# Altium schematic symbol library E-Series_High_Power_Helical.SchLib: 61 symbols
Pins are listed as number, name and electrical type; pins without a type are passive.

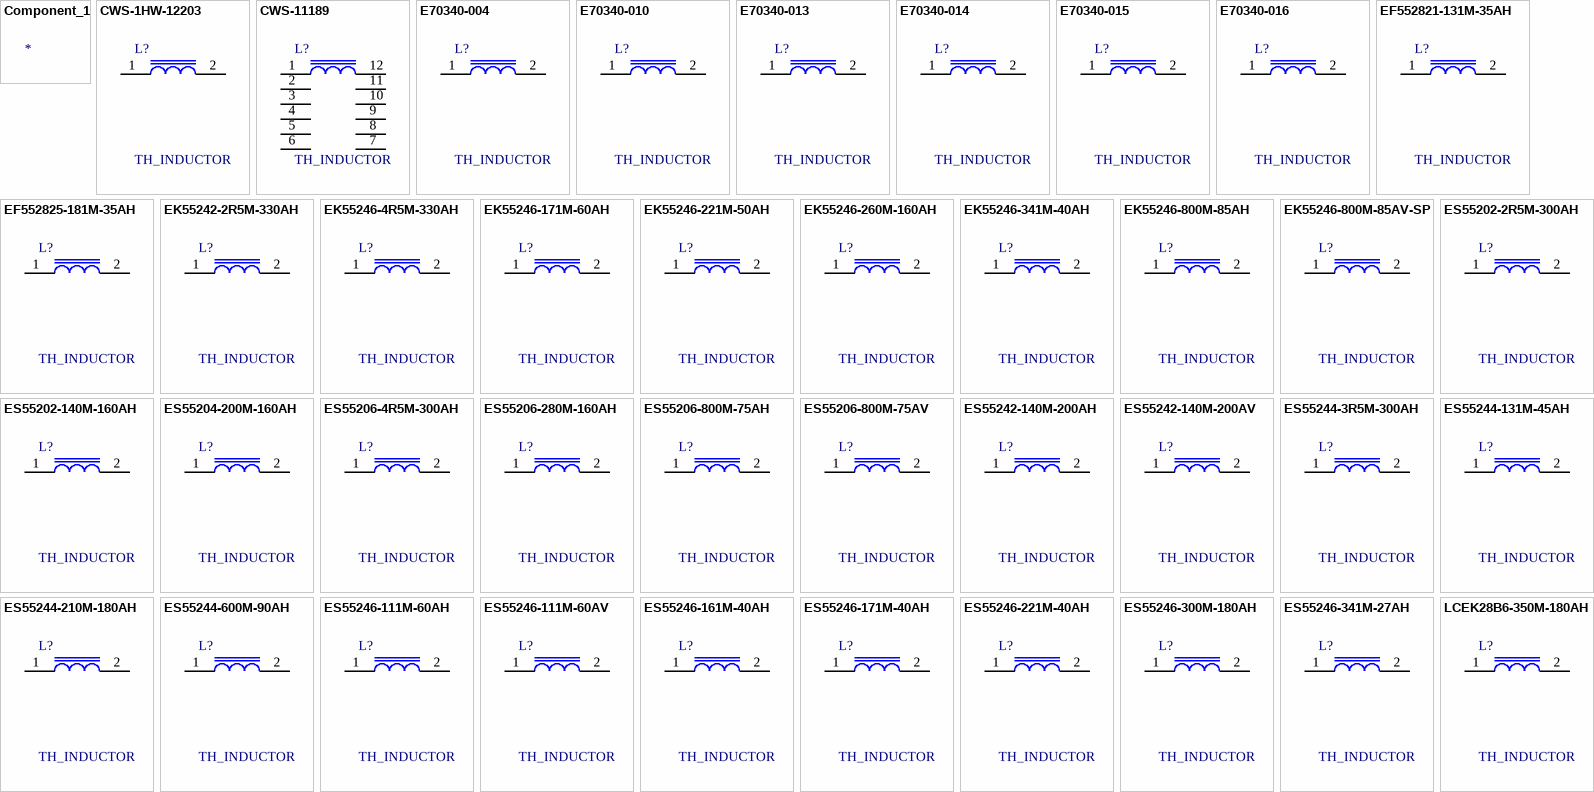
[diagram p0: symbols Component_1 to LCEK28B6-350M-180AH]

## Component_1
designator *  (value not drawn)

## CWS-1HW-12203
designator L?, comment TH_INDUCTOR
POWER INDUCTOR 75 A, 90 uH, 5.0 mOhms, 57.00 mm (L), 45.00 mm (W), 57.00 mm (H); Manufacturer #1: CWS; Sim.Analog.Order: Model$; Current: 75 A; Inductance: 90 uH
footprint CWS-1HW-12203
pins: 1, 2

## CWS-11189
designator L?, comment TH_INDUCTOR
POWER INDUCTOR 25 A, 375 uH, 25 mOhms, 57.00 mm (L), 46.00 mm (W), 39.00 mm (H); Manufacturer #1: CWS; Sim.Analog.Order: Model$; Current: 25 A; Inductance: 375 uH
footprint CWS-11189
pins: 1, 2, 3, 4, 5, 6, 7, 8, 9, 10, 11, 12

## E70340-004
designator L?, comment TH_INDUCTOR
POWER INDUCTOR 120 A, 20 uH, 2.5 mOhms, 43.70 mm (L), 43.70 mm (W), 33.00 mm (H); Manufacturer #1: CWS; Sim.Analog.Order: Model$; Current: 120 A; Inductance: 20 uH
footprint E70340-004
pins: 1, 2

## E70340-010
designator L?, comment TH_INDUCTOR
POWER INDUCTOR 180 A, 12 uH, 0.7 mOhms, 43.70 mm (L), 43.70 mm (W), 33.00 mm (H); Manufacturer #1: CWS; Sim.Analog.Order: Model$; Current: 180 A; Inductance: 12 uH
footprint E70340-010
pins: 1, 2

## E70340-013
designator L?, comment TH_INDUCTOR
POWER INDUCTOR 120 A, 30 uH, 2.0 mOhms, 39.00 mm (L), 39.00 mm (W), 29.00 mm (H); Manufacturer #1: CWS; Sim.Analog.Order: Model$; Current: 120 A; Inductance: 30 uH
footprint E70340-013
pins: 1, 2

## E70340-014
designator L?, comment TH_INDUCTOR
POWER INDUCTOR 150 A, 25 uH, 2.0 mOhms, 44.50 mm (L), 44.50 mm (W), 29.50 mm (H); Manufacturer #1: CWS; Sim.Analog.Order: Model$; Current: 150 A; Inductance: 25 uH
footprint E70340-014
pins: 1, 2

## E70340-015
designator L?, comment TH_INDUCTOR
POWER INDUCTOR 30 A, 150 uH, 12 mOhms, 44.50 mm (L), 44.50 mm (W), 28.40 mm (H); Manufacturer #1: CWS; Sim.Analog.Order: Model$; Current: 30 A; Inductance: 150 uH
footprint E70340-015
pins: 1, 2

## E70340-016
designator L?, comment TH_INDUCTOR
POWER INDUCTOR 30 A, 100 uH, 13 mOhms, 45.00 mm (L), 46.00 mm (W), 28.40 mm (H); Manufacturer #1: CWS; Sim.Analog.Order: Model$; Current: 30 A; Inductance: 100 uH
footprint E70340-016
pins: 1, 2

## EF552821-131M-35AH
designator L?, comment TH_INDUCTOR
POWER INDUCTOR 40 A, 130 uH, 15 mOhms, 67.00 mm (L), 72.00 mm (W), 40.00 mm (H); Manufacturer #1: CWS; Sim.Analog.Order: Model$; Current: 40 A; Inductance: 130 uH
footprint EF552821-131M-35AH
pins: 1, 2

## EF552825-181M-35AH
designator L?, comment TH_INDUCTOR
POWER INDUCTOR 35 A, 180 uH, 15 mOhms, 57.15 mm (L), 56.50 mm (W), 44.15 mm (H); Manufacturer #1: CWS; Sim.Analog.Order: Model$; Current: 35 A; Inductance: 180 uH
footprint EF552825-181M-35AH
pins: 1, 2

## EK55242-2R5M-330AH
designator L?, comment TH_INDUCTOR
POWER INDUCTOR 330 A, 2.5 uH, 0.3 mOhms, 56.00 mm (L), 57.00 mm (W), 36.00 mm (H); Manufacturer #1: CWS; Sim.Analog.Order: Model$; Current: 330 A; Inductance: 2.5 uH
footprint EK55242-2R5M-330AH
pins: 1, 2

## EK55246-4R5M-330AH
designator L?, comment TH_INDUCTOR
POWER INDUCTOR 330 A, 4.5 uH, 0.3 mOhms, 56.00 mm (L), 57.00 mm (W), 36.00 mm (H); Manufacturer #1: CWS; Sim.Analog.Order: Model$; Current: 330 A; Inductance: 4.5 uH
footprint EK55246-4R5M-330AH
pins: 1, 2

## EK55246-171M-60AH
designator L?, comment TH_INDUCTOR
POWER INDUCTOR 60 A, 170 uH, 7.0 mOhms, 58.00 mm (L), 58.00 mm (W), 36.00 mm (H); Manufacturer #1: CWS; Sim.Analog.Order: Model$; Current: 60 A; Inductance: 170 uH
footprint EK55246-171M-60AH
pins: 1, 2

## EK55246-221M-50AH
designator L?, comment TH_INDUCTOR
POWER INDUCTOR 50 A, 220 uH, 12 mOhms, 58.00 mm (L), 58.00 mm (W), 33.00 mm (H); Manufacturer #1: CWS; Sim.Analog.Order: Model$; Current: 50 A; Inductance: 220 uH
footprint EK55246-221M-50AH
pins: 1, 2

## EK55246-260M-160AH
designator L?, comment TH_INDUCTOR
POWER INDUCTOR 160 A, 26 uH, 1.1 mOhms, 58.00 mm (L), 58.00 mm (W), 37.00 mm (H); Manufacturer #1: CWS; Sim.Analog.Order: Model$; Current: 160 A; Inductance: 26 uH
footprint EK55246-260M-160AH
pins: 1, 2

## EK55246-341M-40AH
designator L?, comment TH_INDUCTOR
POWER INDUCTOR 40 A, 340 uH, 13 mOhms, 58.00 mm (L), 58.00 mm (W), 35.00 mm (H); Manufacturer #1: CWS; Sim.Analog.Order: Model$; Current: 40 A; Inductance: 340 uH
footprint EK55246-341M-40AH
pins: 1, 2

## EK55246-800M-85AH
designator L?, comment TH_INDUCTOR
POWER INDUCTOR 85 A, 80 uH, 3.0 mOhms, 58.00 mm (L), 58.00 mm (W), 36.00 mm (H); Manufacturer #1: CWS; Sim.Analog.Order: Model$; Current: 85 A; Inductance: 80 uH
footprint EK55246-800M-85AH
pins: 1, 2

## EK55246-800M-85AV-SP
designator L?, comment TH_INDUCTOR
POWER INDUCTOR 85 A, 80 uH, 3.0 mOhms, 58.00 mm (L), 59.00 mm (W), 42.00 mm (H); Manufacturer #1: CWS; Sim.Analog.Order: Model$; Current: 85 A; Inductance: 80 uH
footprint EK55246-800M-85AV-SP
pins: 1, 2

## ES55202-2R5M-300AH
designator L?, comment TH_INDUCTOR
POWER INDUCTOR 300 A, 2.5 uH, 0.3 mOhms, 56.00 mm (L), 57.00 mm (W), 36.00 mm (H); Manufacturer #1: CWS; Sim.Analog.Order: Model$; Current: 300 A; Inductance: 2.5 uH
footprint ES55202-2R5M-300AH
pins: 1, 2

## ES55202-140M-160AH
designator L?, comment TH_INDUCTOR
POWER INDUCTOR 160 A, 14 uH, 0.9 mOhms, 57.00 mm (L), 57.00 mm (W), 36.00 mm (H); Manufacturer #1: CWS; Sim.Analog.Order: Model$; Current: 160 A; Inductance: 14 uH
footprint ES55202-140M-160AH
pins: 1, 2

## ES55204-200M-160AH
designator L?, comment TH_INDUCTOR
POWER INDUCTOR 160 A, 20 uH, 1.0 mOhms, 57.00 mm (L), 58.00 mm (W), 36.00 mm (H); Manufacturer #1: CWS; Sim.Analog.Order: Model$; Current: 160 A; Inductance: 20 uH
footprint CWS-11189-REV_C 
footprint LCES28B6-391M-40AH-REV_A1
footprint ES55204-200M-160AH
pins: 1, 2

## ES55206-4R5M-300AH
designator L?, comment TH_INDUCTOR
POWER INDUCTOR 300 A, 4.5 uH, 0.3 mOhms, 58.00 mm (L), 58.00 mm (W), 36.20 mm (H); Manufacturer #1: CWS; Sim.Analog.Order: Model$; Current: 300 A; Inductance: 4.5 uH
footprint ES55206-4R5M-300AH
pins: 1, 2

## ES55206-280M-160AH
designator L?, comment TH_INDUCTOR
POWER INDUCTOR 160 A, 28 uH, 0.9 mOhms, 57.00 mm (L), 57.00 mm (W), 35.00 mm (H); Manufacturer #1: CWS; Sim.Analog.Order: Model$; Current: 160 A; Inductance: 28 uH
footprint ES55206-280M-160AH
pins: 1, 2

## ES55206-800M-75AH
designator L?, comment TH_INDUCTOR
POWER INDUCTOR 75 A, 80 uH, 3.0 mOhms, 58.00 mm (L), 58.00 mm (W), 36.00 mm (H); Manufacturer #1: CWS; Sim.Analog.Order: Model$; Current: 75 A; Inductance: 80 uH
footprint ES55206-800M-75AH
pins: 1, 2

## ES55206-800M-75AV
designator L?, comment TH_INDUCTOR
POWER INDUCTOR 75 A, 80 uH, 3.2 mOhms, 58.00 mm (L), 58.00 mm (W), 42.00 mm (H); Manufacturer #1: CWS; Sim.Analog.Order: Model$; Current: 75 A; Inductance: 80 uH
footprint ES55206-800M-75AV
pins: 1, 2

## ES55242-140M-200AH
designator L?, comment TH_INDUCTOR
POWER INDUCTOR 200 A, 14 uH, 1.1 mOhms, 57.00 mm (L), 57.00 mm (W), 38.00 mm (H); Manufacturer #1: CWS; Sim.Analog.Order: Model$; Current: 200 A; Inductance: 14 uH
footprint ES55242-140M-200AH
pins: 1, 2

## ES55242-140M-200AV
designator L?, comment TH_INDUCTOR
POWER INDUCTOR 200 A, 14 uH, 0.9 mOhms, 58.00 mm (L), 58.00 mm (W), 42.00 mm (H); Manufacturer #1: CWS; Sim.Analog.Order: Model$; Current: 200 A; Inductance: 14 uH
footprint ES55242-140M-200AV
pins: 1, 2

## ES55244-3R5M-300AH
designator L?, comment TH_INDUCTOR
POWER INDUCTOR 300 A, 3.5 uH, 0.3 mOhms, 56.00 mm (L), 57.00 mm (W), 36.00 mm (H); Manufacturer #1: CWS; Sim.Analog.Order: Model$; Current: 300 A; Inductance: 3.5 uH
footprint ES55244-3R5M-300AH
pins: 1, 2

## ES55244-131M-45AH
designator L?, comment TH_INDUCTOR
POWER INDUCTOR 45 A, 130 uH, 6.6 mOhms, 58.00 mm (L), 58.00 mm (W), 36.00 mm (H); Manufacturer #1: CWS; Sim.Analog.Order: Model$; Current: 45 A; Inductance: 130 uH
footprint ES55244-131M-45AH
pins: 1, 2

## ES55244-210M-180AH
designator L?, comment TH_INDUCTOR
POWER INDUCTOR 180 A, 21 uH, 0.9 mOhms, 58.00 mm (L), 58.00 mm (W), 36.00 mm (H); Manufacturer #1: CWS; Sim.Analog.Order: Model$; Current: 180 A; Inductance: 21 uH
footprint ES55244-210M-180AH
pins: 1, 2

## ES55244-600M-90AH
designator L?, comment TH_INDUCTOR
POWER INDUCTOR 90 A, 60 uH, 3.0 mOhms, 58.00 mm (L), 58.00 mm (W), 36.00 mm (H); Manufacturer #1: CWS; Sim.Analog.Order: Model$; Current: 90 A; Inductance: 60 uH
footprint ES55244-600M-90AH
pins: 1, 2

## ES55246-111M-60AH
designator L?, comment TH_INDUCTOR
POWER INDUCTOR 60 A, 110 uH, 3.5 mOhms, 58.00 mm (L), 58.00 mm (W), 36.00 mm (H); Manufacturer #1: CWS; Sim.Analog.Order: Model$; Current: 60 A; Inductance: 110 uH
footprint ES55246-111M-60AH
pins: 1, 2

## ES55246-111M-60AV
designator L?, comment TH_INDUCTOR
POWER INDUCTOR 60 A, 110 uH, 4.0 mOhms, 58.00 mm (L), 58.00 mm (W), 42.00 mm (H); Manufacturer #1: CWS; Sim.Analog.Order: Model$; Current: 60 A; Inductance: 110 uH
footprint ES55246-111M-60AV
pins: 1, 2

## ES55246-161M-40AH
designator L?, comment TH_INDUCTOR
POWER INDUCTOR 40 A, 160 uH, 15 mOhms, 58.00 mm (L), 58.00 mm (W), 36.00 mm (H); Manufacturer #1: CWS; Sim.Analog.Order: Model$; Current: 40 A; Inductance: 160 uH
footprint ES55246-161M-40AH
pins: 1, 2

## ES55246-171M-40AH
designator L?, comment TH_INDUCTOR
POWER INDUCTOR 40 A, 170 uH, 6.9 mOhms, 58.00 mm (L), 58.00 mm (W), 36.00 mm (H); Manufacturer #1: CWS; Sim.Analog.Order: Model$; Current: 40 A; Inductance: 170 uH
footprint ES55246-171M-40AH
pins: 1, 2

## ES55246-221M-40AH
designator L?, comment TH_INDUCTOR
POWER INDUCTOR 40 A, 220 uH, 9.7 mOhms, 58.00 mm (L), 58.00 mm (W), 34.00 mm (H); Manufacturer #1: CWS; Sim.Analog.Order: Model$; Current: 40 A; Inductance: 220 uH
footprint ES55246-221M-40AH
pins: 1, 2

## ES55246-300M-180AH
designator L?, comment TH_INDUCTOR
POWER INDUCTOR 180 A, 30 uH, 1.0 mOhms, 57.00 mm (L), 57.00 mm (W), 35.00 mm (H); Manufacturer #1: CWS; Sim.Analog.Order: Model$; Current: 180 A; Inductance: 30 uH
footprint ES55246-300M-180AH
pins: 1, 2

## ES55246-341M-27AH
designator L?, comment TH_INDUCTOR
POWER INDUCTOR 27 A, 340 uH, 13 mOhms, 58.00 mm (L), 58.00 mm (W), 35.00 mm (H); Manufacturer #1: CWS; Sim.Analog.Order: Model$; Current: 27 A; Inductance: 340 uH
footprint ES55246-341M-27AH
pins: 1, 2

## LCEK28B6-350M-180AH
designator L?, comment TH_INDUCTOR
POWER INDUCTOR 50 A, 350 uH, 11 mOhms, 57.15 mm (L), 57.15 mm (W), 44.15 mm (H); Manufacturer #1: CWS; Sim.Analog.Order: Model$; Current: 50 A; Inductance: 350 uH
footprint LCEK28B62-351M-50AH
pins: 1, 2

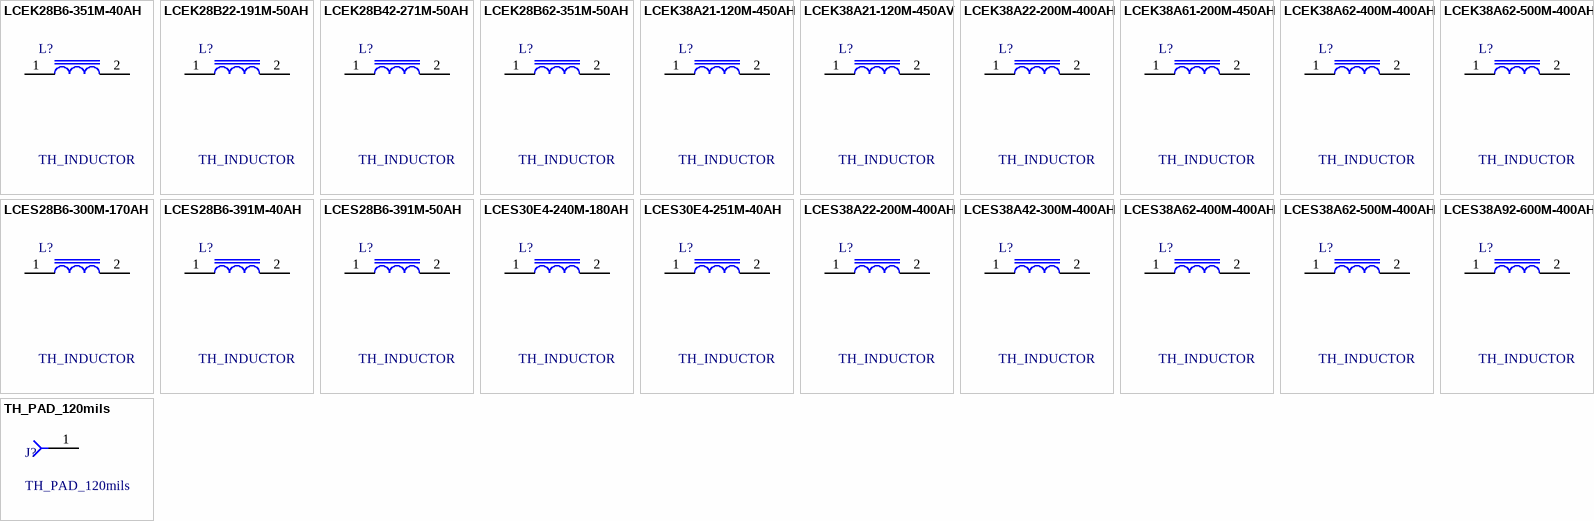
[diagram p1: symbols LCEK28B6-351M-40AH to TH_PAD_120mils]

## LCEK28B6-351M-40AH
designator L?, comment TH_INDUCTOR
POWER INDUCTOR 180 A, 35 uH, 1.2 mOhms, 57.15 mm (L), 57.15 mm (W), 46.70 mm (H); Manufacturer #1: CWS; Sim.Analog.Order: Model$; Current: 180 A; Inductance: 35 uH
footprint LCEK28B6-350M-180AH
pins: 1, 2

## LCEK28B22-191M-50AH
designator L?, comment TH_INDUCTOR
POWER INDUCTOR 50 A, 190 uH, 11 mOhms, 58.50 mm (L), 58.50 mm (W), 73.00 mm (H); Manufacturer #1: CWS; Sim.Analog.Order: Model$; Current: 50 A; Inductance: 190 uH
footprint LCEK28B22-191M-50AH
pins: 1, 2

## LCEK28B42-271M-50AH
designator L?, comment TH_INDUCTOR
POWER INDUCTOR 50 A, 270 uH, 11 mOhms, 58.50 mm (L), 58.50 mm (W), 73.00 mm (H); Manufacturer #1: CWS; Sim.Analog.Order: Model$; Current: 50 A; Inductance: 270 uH
footprint LCEK28B42-271M-50AH
pins: 1, 2

## LCEK28B62-351M-50AH
designator L?, comment TH_INDUCTOR
POWER INDUCTOR 40 A, 350 uH, 15 mOhms, 57.15 mm (L), 57.15 mm (W), 44.15 mm (H); Manufacturer #1: CWS; Sim.Analog.Order: Model$; Current: 40 A; Inductance: 350 uH
footprint LCEK28B6-351M-40AH
pins: 1, 2

## LCEK38A21-120M-450AH
designator L?, comment TH_INDUCTOR
POWER INDUCTOR 450 A, 12 uH, 0.6 mOhms, 82.00 mm (L), 79.00 mm (W), 55.00 mm (H); Manufacturer #1: CWS; Sim.Analog.Order: Model$; Current: 450 A; Inductance: 12 uH
footprint LCEK38A21-120M-450AH
pins: 1, 2

## LCEK38A21-120M-450AV
designator L?, comment TH_INDUCTOR
POWER INDUCTOR 450 A, 12 uH, 0.6 mOhms, 80.00 mm (L), 56.50 mm (W), 81.50 mm (H); Manufacturer #1: CWS; Sim.Analog.Order: Model$; Current: 450 A; Inductance: 12 uH
footprint LCEK38A21-120M-450AV
pins: 1, 2

## LCEK38A22-200M-400AH
designator L?, comment TH_INDUCTOR
POWER INDUCTOR 400 A, 20 uH, 0.8 mOhms, 82.50 mm (L), 78.55mm (W), 79.00 mm (H); Manufacturer #1: CWS; Sim.Analog.Order: Model$; Current: 400 A; Inductance: 20 uH
footprint LCEK38A22-200M-400AH
pins: 1, 2

## LCEK38A61-200M-450AH
designator L?, comment TH_INDUCTOR
POWER INDUCTOR 450 A, 20 uH, 0.6 mOhms, 82.00 mm (L), 79.00 mm (W), 55.00 mm (H); Manufacturer #1: CWS; Sim.Analog.Order: Model$; Current: 450 A; Inductance: 20 uH
footprint LCEK38A61-200M-450AH
pins: 1, 2

## LCEK38A62-400M-400AH
designator L?, comment TH_INDUCTOR
POWER INDUCTOR 400 A, 40 uH, 0.8 mOhms, 82.50 mm (L), 80.00 mm (W), 80.00 mm (H); Manufacturer #1: CWS; Sim.Analog.Order: Model$; Current: 400 A; Inductance: 40 uH
footprint LCEK38A62-400M-400AH
pins: 1, 2

## LCEK38A62-500M-400AH
designator L?, comment TH_INDUCTOR
POWER INDUCTOR 400 A, 50 uH, 0.7 mOhms, 82.50 mm (L), 80.00 mm (W), 80.00 mm (H); Manufacturer #1: CWS; Sim.Analog.Order: Model$; Current: 400 A; Inductance: 50 uH
footprint LCEK38A62-500M-400AH
pins: 1, 2

## LCES28B6-300M-170AH
designator L?, comment TH_INDUCTOR
POWER INDUCTOR 170 A, 30 uH, 1.2 mOhms, 57.00 mm (L), 57.00 mm (W), 44.25 mm (H); Manufacturer #1: CWS; Sim.Analog.Order: Model$; Current: 170 A; Inductance: 30 uH
footprint LCES28B6-391M-50AH
pins: 1, 2

## LCES28B6-391M-40AH
designator L?, comment TH_INDUCTOR
POWER INDUCTOR 40 A, 390 uH, 15 mOhms, 57.15 mm (L), 57.15 mm (W), 44.15 mm (H); Manufacturer #1: CWS; Sim.Analog.Order: Model$; Current: 40 A; Inductance: 390 uH
footprint LCES28B6-300M-170AH
pins: 1, 2

## LCES28B6-391M-50AH
designator L?, comment TH_INDUCTOR
POWER INDUCTOR 50 A, 390 uH, 11 mOhms, 58.50 mm (L), 58.50 mm (W), 73.00 mm (H); Manufacturer #1: CWS; Sim.Analog.Order: Model$; Current: 50 A; Inductance: 390 uH
footprint LCES28B6-391M-40AH
pins: 1, 2

## LCES30E4-240M-180AH
designator L?, comment TH_INDUCTOR
POWER INDUCTOR 180 A, 24 uH, 1.2 mOhms, 57.15 mm (L), 57.15 mm (W), 46.70 mm (H); Manufacturer #1: CWS; Sim.Analog.Order: Model$; Current: 180 A; Inductance: 24 uH
footprint LCES30E4-240M-180AH
pins: 1, 2

## LCES30E4-251M-40AH
designator L?, comment TH_INDUCTOR
POWER INDUCTOR 40 A, 250 uH, 15 mOhms, 57.15 mm (L), 57.15 mm (W), 44.15 mm (H); Manufacturer #1: CWS; Sim.Analog.Order: Model$; Current: 40 A; Inductance: 250 uH
footprint LCES30E4-251M-40AH
pins: 1, 2

## LCES38A22-200M-400AH
designator L?, comment TH_INDUCTOR
POWER INDUCTOR 400 A, 20 uH, 0.8 mOhms, 82.50 mm (L), 80.00 mm (W), 80.00 mm (H); Manufacturer #1: CWS; Sim.Analog.Order: Model$; Current: 400 A; Inductance: 20 uH
footprint LCES38A22-200M-400AH
pins: 1, 2

## LCES38A42-300M-400AH
designator L?, comment TH_INDUCTOR
POWER INDUCTOR 400 A, 30 uH, 0.8 mOhms, 82.50 mm (L), 80.00 mm (W), 80.00 mm (H); Manufacturer #1: CWS; Sim.Analog.Order: Model$; Current: 400 A; Inductance: 30 uH
footprint LCES38A42-300M-400AH
pins: 1, 2

## LCES38A62-400M-400AH
designator L?, comment TH_INDUCTOR
POWER INDUCTOR 400 A, 40 uH, 0.8 mOhms, 82.50 mm (L), 80.00 mm (W), 80.00 mm (H); Manufacturer #1: CWS; Sim.Analog.Order: Model$; Current: 400 A; Inductance: 40 uH
footprint LCES38A62-400M-400AH
pins: 1, 2

## LCES38A62-500M-400AH
designator L?, comment TH_INDUCTOR
POWER INDUCTOR 400 A, 50 uH, 0.8 mOhms, 82.50 mm (L), 80.00 mm (W), 80.00 mm (H); Manufacturer #1: CWS; Sim.Analog.Order: Model$; Current: 400 A; Inductance: 50 uH
footprint LCES38A62-500M-400AH
pins: 1, 2

## LCES38A92-600M-400AH
designator L?, comment TH_INDUCTOR
POWER INDUCTOR 400 A, 60 uH, 0.8 mOhms, 82.50 mm (L), 80.00 mm (W), 80.00 mm (H); Manufacturer #1: CWS; Sim.Analog.Order: Model$; Current: 400 A; Inductance: 60 uH
footprint LCES38A92-600M-400AH
pins: 1, 2

## TH_PAD_120mils
designator J?
footprint 1X2_0.1_CONN
footprint TH_PAD_120mils
pins: 1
